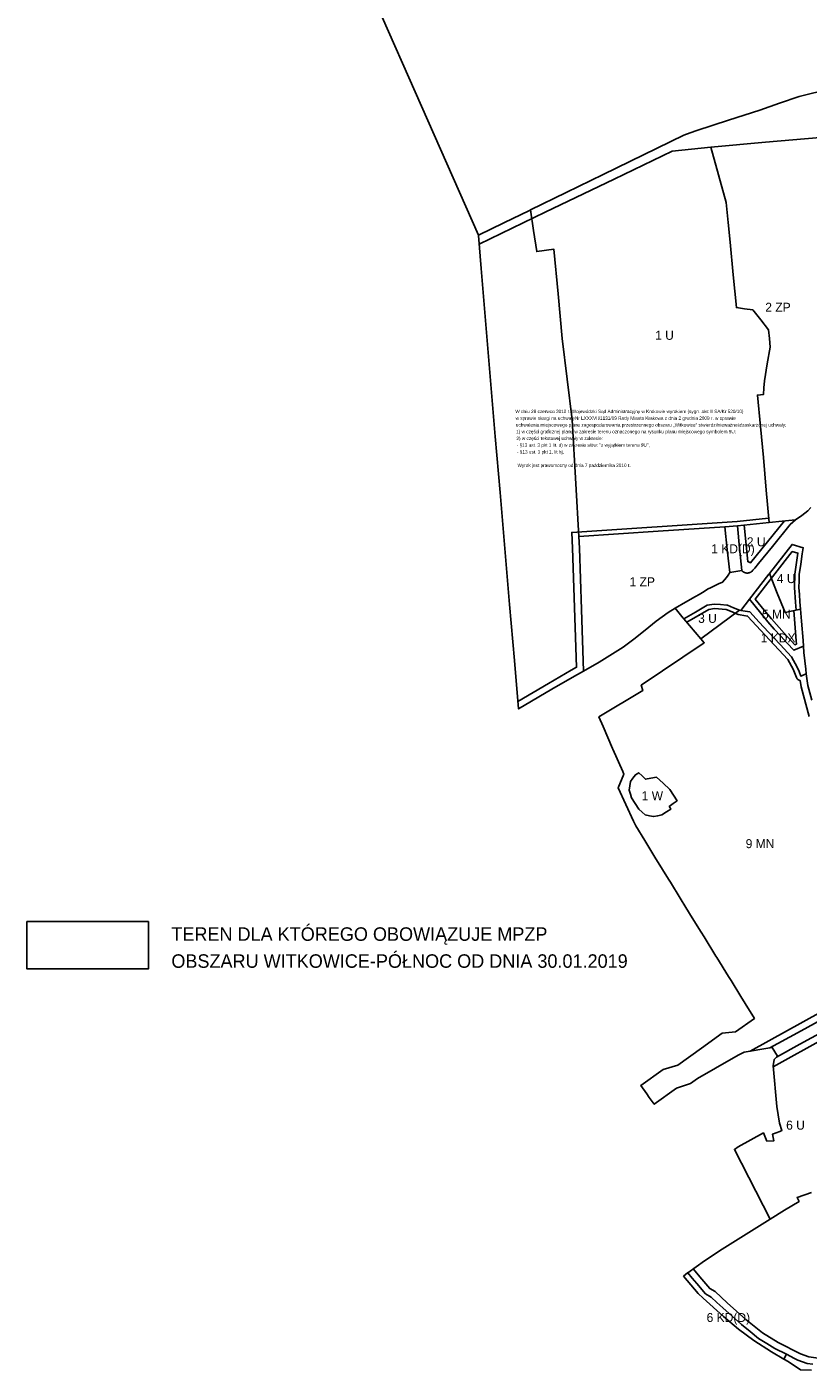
# Model space of a CAD drawing. Extents: x 7423691 to 7425475, y 5552085 to 5554331.
# Drawn here: x 7423691 to 7424385, y 5552233 to 5553427 of the extents above; entities that cross this region are included whole.
import ezdxf

# ---------------------------------------------------------------- set-up
doc = ezdxf.new("R2010")
doc.units = 0
for name, color, linetype in [('linia_zabudowy_nieprzekraczalna', 7, 'Continuous'), ('linie_rozgraniczajace', 7, 'Continuous'), ('oznaczenia_przeznaczen', 7, 'Continuous'), ('Witkowice_Północ', 7, 'Continuous')]:
    doc.layers.add(name, color=color, linetype=linetype)

msp = doc.modelspace()

# ---------------------------------------------------------------- linework, layer by layer
at = {"layer": 'linia_zabudowy_nieprzekraczalna'}
for points in [[(7424298.81, 5553320.3), (7424264.38, 5553316.64), (7424212.77, 5553291.84), (7424151.55, 5553262.41), (7424092.82, 5553234.06)], [(7424127.29, 5552827.27), (7424154.54, 5552843.37), (7424174.66, 5552855.11), (7424179.44, 5552857.77), (7424175.9, 5552963.47), (7424175.11, 5552977.64), (7424322.2, 5552987.46), (7424350.09, 5552990.32)], [(7424328.51, 5552984.08), (7424331.55, 5552951.67), (7424333.94, 5552950.56), (7424364.31, 5552987.77)], [(7424372.58, 5552908.11), (7424374.77, 5552881.2), (7424374.92, 5552878.26), (7424373.57, 5552877.7), (7424363.83, 5552888.08), (7424352.56, 5552900.66), (7424346.09, 5552908.44), (7424338.3, 5552918.22), (7424371.15, 5552960.64), (7424376.12, 5552959.29), (7424376.12, 5552959.29), (7424373.38, 5552940.61), (7424373.08, 5552928.5), (7424373.97, 5552915.68), (7424374.56, 5552908.48)], [(7424335.78, 5552914.96), (7424335.48, 5552914.58)], [(7424277.33, 5552897.7), (7424296.98, 5552908.96), (7424302, 5552909.9), (7424312.48, 5552909.08), (7424316.21, 5552907.66), (7424323.09, 5552904.53), (7424324.84, 5552904.25), (7424324.84, 5552904.25), (7424331.39, 5552903.18), (7424347.14, 5552886.09), (7424367.36, 5552864.64), (7424372.07, 5552855.92), (7424374.97, 5552848.52), (7424375.2, 5552848.01), (7424375.49, 5552847.54), (7424375.84, 5552847.11), (7424376.26, 5552846.73), (7424376.73, 5552846.41), (7424377.23, 5552846.17), (7424377.75, 5552846), (7424378.27, 5552845.9), (7424378.95, 5552840.23), (7424386.33, 5552813.96)], [(7424397.48, 5552551.4), (7424333.75, 5552516.27)], [(7424400.4, 5552408.64), (7424408.18, 5552408.95), (7424416.39, 5552416.19), (7424421.51, 5552418.39), (7424444.81, 5552427.53), (7424458.27, 5552433.41), (7424452.84, 5552443), (7424451.24, 5552444.38), (7424431.75, 5552461.23), (7424426.13, 5552466.13), (7424417.13, 5552487.94), (7424407.39, 5552511.01), (7424400.18, 5552527.77), (7424354.16, 5552502.4)], [(7424283.11, 5552322.72), (7424290.92, 5552313.42), (7424297.88, 5552305.19), (7424302.65, 5552302.46), (7424313.35, 5552292.4), (7424329.92, 5552277.7), (7424344.76, 5552265.77), (7424358.71, 5552257.06), (7424378.55, 5552246.99), (7424385.8, 5552244.36), (7424394.2, 5552243.19), (7424396.85, 5552243.7), (7424410.23, 5552249.51)]]:
    msp.add_lwpolyline(points, dxfattribs=at)
at = {"layer": 'linie_rozgraniczajace'}
for points in [[(7424404.09, 5553447.74), (7424402.84, 5553403.8), (7424402.46, 5553397.12), (7424401.72, 5553383.77), (7424400.72, 5553370.96), (7424389.05, 5553368.17), (7424377.38, 5553365.38), (7424359.9, 5553359.31), (7424342.42, 5553353.25), (7424314.38, 5553344.13), (7424286.34, 5553335.02), (7424280.52, 5553333), (7424274.69, 5553330.99), (7424238.8, 5553313.52), (7424202.92, 5553296.05), (7424170.19, 5553280.04), (7424138.53, 5553264.56), (7424137.46, 5553264.03), (7424114.78, 5553252.97), (7424092.11, 5553241.91), (7423950.32, 5553563.7)], [(7424395.95, 5553328.82), (7424347.38, 5553324.56), (7424298.81, 5553320.3), (7424305.68, 5553295.65), (7424312.55, 5553271.01), (7424314.25, 5553253.36), (7424315.94, 5553235.71), (7424318.74, 5553206.62), (7424321.54, 5553177.54), (7424328.82, 5553176.51), (7424336.09, 5553175.48), (7424343.09, 5553166.67), (7424350.09, 5553157.85), (7424350.83, 5553150.18), (7424351.57, 5553142.5), (7424348.97, 5553127.41), (7424346.37, 5553112.32), (7424345.99, 5553106.32), (7424345.61, 5553100.32), (7424342.87, 5553100.01), (7424340.12, 5553099.71), (7424342.87, 5553071.95), (7424345.62, 5553044.18), (7424348.06, 5553015.26), (7424350.5, 5552986.34), (7424322.62, 5552983.48), (7424322.54, 5552983.47), (7424311.28, 5552982.72), (7424251.93, 5552978.76), (7424181.32, 5552974.05), (7424178.71, 5553020.69), (7424175.53, 5553077.61), (7424171.11, 5553113.79), (7424166.69, 5553149.96), (7424162.93, 5553189.75), (7424159.16, 5553229.53), (7424143.96, 5553227.43), (7424141.25, 5553245.99), (7424138.53, 5553264.56), (7424170.19, 5553280.04), (7424202.92, 5553296.05), (7424238.8, 5553313.52), (7424274.69, 5553330.99), (7424280.52, 5553333), (7424286.34, 5553335.02), (7424314.38, 5553344.13), (7424342.42, 5553353.25), (7424359.9, 5553359.31), (7424377.38, 5553365.38), (7424389.05, 5553368.17)], [(7424387.6, 5552999.9), (7424385.05, 5552996.71), (7424379.54, 5552992.74), (7424374.03, 5552988.77), (7424362.26, 5552987.56), (7424350.5, 5552986.34), (7424348.06, 5553015.26), (7424345.62, 5553044.18), (7424342.87, 5553071.95), (7424340.12, 5553099.71), (7424342.87, 5553100.01), (7424345.61, 5553100.32), (7424345.99, 5553106.32), (7424346.37, 5553112.32), (7424348.97, 5553127.41), (7424351.57, 5553142.5), (7424350.83, 5553150.18), (7424350.09, 5553157.85), (7424343.09, 5553166.67), (7424336.09, 5553175.48), (7424328.82, 5553176.51), (7424321.54, 5553177.54), (7424318.74, 5553206.62), (7424315.94, 5553235.71), (7424314.25, 5553253.36), (7424312.55, 5553271.01), (7424305.68, 5553295.65), (7424298.81, 5553320.3), (7424347.38, 5553324.56), (7424395.95, 5553328.82)], [(7424267.08, 5552910.22), (7424276.18, 5552915.44), (7424285.28, 5552920.66), (7424288.33, 5552922.43), (7424291.38, 5552924.19), (7424293.64, 5552925.63), (7424295.9, 5552927.05), (7424298.94, 5552928.63), (7424301.98, 5552930.21), (7424305.58, 5552931.75), (7424309.19, 5552933.3), (7424310.92, 5552935.42), (7424312.65, 5552937.55), (7424314.09, 5552939.69), (7424315.52, 5552941.84), (7424320.89, 5552942.79), (7424326.27, 5552943.73), (7424326.37, 5552943.61), (7424326.48, 5552943.49), (7424326.59, 5552943.37), (7424326.71, 5552943.26), (7424326.82, 5552943.15), (7424326.94, 5552943.04), (7424327.07, 5552942.94), (7424327.19, 5552942.84), (7424327.32, 5552942.74), (7424327.45, 5552942.65), (7424327.58, 5552942.56), (7424327.71, 5552942.47), (7424327.85, 5552942.39), (7424327.99, 5552942.31), (7424328.13, 5552942.23), (7424328.27, 5552942.16), (7424328.41, 5552942.09), (7424328.56, 5552942.02), (7424328.71, 5552941.96), (7424328.86, 5552941.9), (7424329.01, 5552941.84), (7424329.16, 5552941.79), (7424329.31, 5552941.74), (7424329.46, 5552941.7), (7424329.62, 5552941.66), (7424329.78, 5552941.62), (7424329.93, 5552941.59), (7424330.09, 5552941.56), (7424330.25, 5552941.54), (7424330.41, 5552941.52), (7424330.57, 5552941.5), (7424330.73, 5552941.49), (7424330.89, 5552941.48), (7424331.05, 5552941.47), (7424331.21, 5552941.47), (7424331.37, 5552941.48), (7424331.53, 5552941.48), (7424331.69, 5552941.5), (7424331.84, 5552941.51), (7424332, 5552941.53), (7424332.16, 5552941.55), (7424332.32, 5552941.58), (7424332.48, 5552941.61), (7424332.63, 5552941.65), (7424332.79, 5552941.69), (7424332.94, 5552941.73), (7424333.09, 5552941.78), (7424333.25, 5552941.83), (7424333.4, 5552941.88), (7424333.55, 5552941.94), (7424333.69, 5552942), (7424333.84, 5552942.07), (7424333.99, 5552942.14), (7424334.13, 5552942.21), (7424334.27, 5552942.29), (7424334.41, 5552942.36), (7424334.54, 5552942.45), (7424334.68, 5552942.53), (7424334.81, 5552942.62), (7424334.84, 5552942.64), (7424335.16, 5552942.98), (7424336.19, 5552944.08), (7424337.75, 5552945.73), (7424341.24, 5552950.01), (7424353.58, 5552965.14), (7424369.42, 5552984.54), (7424371.72, 5552986.66), (7424374.03, 5552988.77), (7424379.54, 5552992.74), (7424385.05, 5552996.71), (7424387.6, 5552999.9)], [(7424388.5, 5552828.42), (7424384.86, 5552841.41), (7424383.61, 5552851.8), (7424383.09, 5552856.1), (7424381.33, 5552870.79), (7424381.03, 5552876.44), (7424380.75, 5552881.6), (7424379.36, 5552898.79), (7424378.5, 5552909.37), (7424377.96, 5552915.98), (7424377.52, 5552922.29), (7424377.09, 5552928.59), (7424377.23, 5552934.43), (7424377.37, 5552940.27), (7424378.72, 5552949.46), (7424380.06, 5552958.66), (7424380.99, 5552964.04), (7424370.98, 5552966.96), (7424350.94, 5552941.07), (7424350.42, 5552940.4), (7424333.21, 5552918.18), (7424329.44, 5552913.31), (7424325.47, 5552908.19), (7424324.26, 5552908.39), (7424318.91, 5552910.67), (7424313.57, 5552912.96), (7424313.13, 5552913.04), (7424307.46, 5552913.48), (7424301.79, 5552913.93), (7424295.58, 5552912.77), (7424285.12, 5552906.77), (7424274.67, 5552900.79), (7424274.28, 5552901.25), (7424267.08, 5552910.22)], [(7424400.02, 5552545.95), (7424375.69, 5552532.54), (7424351.36, 5552519.13), (7424328.49, 5552515.42), (7424323.16, 5552512.68), (7424303.07, 5552501.21), (7424286.83, 5552491.94), (7424280.72, 5552487.55), (7424268.37, 5552483.32), (7424248.47, 5552469.03), (7424244.05, 5552475.18), (7424241.74, 5552478.41), (7424236.52, 5552485.68), (7424256.41, 5552499.97), (7424269.34, 5552503.71), (7424290.35, 5552518.81), (7424308.94, 5552532.15), (7424320.82, 5552533.36), (7424337.45, 5552545.4), (7424329.3, 5552558.63), (7424325.36, 5552565.02), (7424316.73, 5552579.01), (7424314.57, 5552582.53), (7424304.08, 5552599.57), (7424303.34, 5552600.77), (7424292.75, 5552617.95), (7424290.2, 5552622.09), (7424282.29, 5552634.94), (7424276.64, 5552644.1), (7424271.61, 5552652.27), (7424262.85, 5552666.5), (7424261.09, 5552669.35), (7424250.57, 5552686.42), (7424250, 5552687.35), (7424240.06, 5552703.49), (7424231.98, 5552716.59), (7424230.01, 5552720.91), (7424216.5, 5552750.39), (7424221.41, 5552762.6), (7424220.41, 5552764.89), (7424211.68, 5552784.97), (7424211.45, 5552785.52), (7424203, 5552804.98), (7424199.28, 5552813.54), (7424238.27, 5552837.01), (7424236.9, 5552841.75), (7424292.94, 5552879.5), (7424289.92, 5552883.01), (7424307.09, 5552895.7), (7424324.26, 5552908.39), (7424325.47, 5552908.19), (7424329.43, 5552907.55), (7424333.39, 5552906.91), (7424341.87, 5552897.72), (7424350.07, 5552888.82), (7424360.29, 5552877.98), (7424370.63, 5552867), (7424375.59, 5552857.82), (7424377.16, 5552853.84), (7424378.73, 5552849.87), (7424383.61, 5552851.8), (7424384.86, 5552841.41), (7424388.5, 5552828.42)], [(7424388.29, 5552390.66), (7424375.49, 5552386.27), (7424376.36, 5552384.46), (7424377.23, 5552382.65), (7424364.4, 5552374.76), (7424351.42, 5552366.78), (7424351.57, 5552366.87), (7424319.81, 5552428.85), (7424322.99, 5552431.29), (7424345.45, 5552443.59), (7424348.57, 5552436.25), (7424354.88, 5552436.58), (7424353.57, 5552442.32), (7424360.21, 5552444.81), (7424361.97, 5552445.64), (7424359.74, 5552452.27), (7424357.59, 5552467.12), (7424354.07, 5552503.28), (7424355.1, 5552508.75), (7424357.25, 5552510.96), (7424377.97, 5552522.38), (7424398.69, 5552533.8)], [(7424389.35, 5552237.81), (7424384.35, 5552238.5), (7424380.26, 5552239.99), (7424376.16, 5552241.47), (7424373.22, 5552242.97), (7424365.96, 5552246.65), (7424355.76, 5552251.83), (7424348.52, 5552256.35), (7424341.28, 5552260.87), (7424333.66, 5552266.99), (7424326.04, 5552273.12), (7424317.68, 5552280.54), (7424309.31, 5552287.97), (7424304.18, 5552292.78), (7424299.06, 5552297.6), (7424293.98, 5552300.51), (7424286.34, 5552309.55), (7424282.26, 5552314.4), (7424278.19, 5552319.25), (7424293.03, 5552329.74), (7424308.85, 5552340.26), (7424351.42, 5552366.78), (7424364.4, 5552374.76), (7424377.23, 5552382.65), (7424376.36, 5552384.46), (7424375.49, 5552386.27), (7424388.29, 5552390.66)], [(7424388.34, 5552232.59), (7424378.48, 5552232.85), (7424367.61, 5552240.22), (7424363.78, 5552242.4), (7424365.96, 5552246.65), (7424373.22, 5552242.97), (7424376.16, 5552241.47), (7424380.26, 5552239.99), (7424384.35, 5552238.5), (7424389.35, 5552237.81)]]:
    msp.add_lwpolyline(points, dxfattribs=at)
for points in [[(7424092.11, 5553241.91), (7424114.78, 5553252.97), (7424137.46, 5553264.03), (7424138.53, 5553264.56), (7424141.25, 5553245.99), (7424143.96, 5553227.43), (7424159.16, 5553229.53), (7424162.93, 5553189.75), (7424166.69, 5553149.96), (7424171.11, 5553113.79), (7424175.53, 5553077.61), (7424178.71, 5553020.69), (7424181.32, 5552974.05), (7424181.89, 5552963.74), (7424183.73, 5552909.03), (7424185.56, 5552854.31), (7424177.63, 5552849.89), (7424157.57, 5552838.2), (7424127.86, 5552820.64), (7424124.09, 5552863.72), (7424119.81, 5552913.52), (7424115.57, 5552963.31), (7424111.39, 5553013.12), (7424107.11, 5553062.92), (7424102.97, 5553112.73), (7424098.73, 5553162.53), (7424094.7, 5553212.35), (7424092.15, 5553241.81)], [(7424185.56, 5552854.31), (7424183.73, 5552909.03), (7424181.89, 5552963.74), (7424181.32, 5552974.05), (7424251.93, 5552978.76), (7424311.28, 5552982.72), (7424313.4, 5552962.28), (7424315.52, 5552941.84), (7424314.09, 5552939.69), (7424312.65, 5552937.55), (7424310.92, 5552935.42), (7424309.19, 5552933.3), (7424305.58, 5552931.75), (7424301.98, 5552930.21), (7424298.94, 5552928.63), (7424295.9, 5552927.05), (7424293.64, 5552925.63), (7424291.38, 5552924.19), (7424288.33, 5552922.43), (7424285.28, 5552920.66), (7424276.18, 5552915.44), (7424267.08, 5552910.22), (7424267.03, 5552910.28), (7424260.77, 5552906.29), (7424250.17, 5552898.63), (7424240.5, 5552890.8), (7424230.46, 5552882.68), (7424220.72, 5552875.51), (7424199.59, 5552862.08)], [(7424311.28, 5552982.72), (7424322.54, 5552983.47), (7424322.62, 5552983.48), (7424324.4, 5552963.6), (7424326.27, 5552943.73), (7424320.89, 5552942.79), (7424315.52, 5552941.84), (7424313.4, 5552962.28)], [(7424322.62, 5552983.48), (7424350.5, 5552986.34), (7424362.26, 5552987.56), (7424374.03, 5552988.77), (7424371.72, 5552986.66), (7424369.42, 5552984.54), (7424353.58, 5552965.14), (7424341.24, 5552950.01), (7424337.75, 5552945.73), (7424336.19, 5552944.08), (7424335.16, 5552942.98), (7424334.84, 5552942.64), (7424334.81, 5552942.62), (7424334.68, 5552942.53), (7424334.54, 5552942.45), (7424334.41, 5552942.36), (7424334.27, 5552942.29), (7424334.13, 5552942.21), (7424333.99, 5552942.14), (7424333.84, 5552942.07), (7424333.69, 5552942), (7424333.55, 5552941.94), (7424333.4, 5552941.88), (7424333.25, 5552941.83), (7424333.09, 5552941.78), (7424332.94, 5552941.73), (7424332.79, 5552941.69), (7424332.63, 5552941.65), (7424332.48, 5552941.61), (7424332.32, 5552941.58), (7424332.16, 5552941.55), (7424332, 5552941.53), (7424331.84, 5552941.51), (7424331.69, 5552941.5), (7424331.53, 5552941.48), (7424331.37, 5552941.48), (7424331.21, 5552941.47), (7424331.05, 5552941.47), (7424330.89, 5552941.48), (7424330.73, 5552941.49), (7424330.57, 5552941.5), (7424330.41, 5552941.52), (7424330.25, 5552941.54), (7424330.09, 5552941.56), (7424329.93, 5552941.59), (7424329.78, 5552941.62), (7424329.62, 5552941.66), (7424329.46, 5552941.7), (7424329.31, 5552941.74), (7424329.16, 5552941.79), (7424329.01, 5552941.84), (7424328.86, 5552941.9), (7424328.71, 5552941.96), (7424328.56, 5552942.02), (7424328.41, 5552942.09), (7424328.27, 5552942.16), (7424328.13, 5552942.23), (7424327.99, 5552942.31), (7424327.85, 5552942.39), (7424327.71, 5552942.47), (7424327.58, 5552942.56), (7424327.45, 5552942.65), (7424327.32, 5552942.74), (7424327.19, 5552942.84), (7424327.07, 5552942.94), (7424326.94, 5552943.04), (7424326.82, 5552943.15), (7424326.71, 5552943.26), (7424326.59, 5552943.37), (7424326.48, 5552943.49), (7424326.37, 5552943.61), (7424326.27, 5552943.73), (7424324.4, 5552963.6)], [(7424350.94, 5552941.07), (7424370.98, 5552966.96), (7424380.99, 5552964.04), (7424380.06, 5552958.66), (7424378.72, 5552949.46), (7424377.37, 5552940.27), (7424377.23, 5552934.43), (7424377.09, 5552928.59), (7424377.52, 5552922.29), (7424377.96, 5552915.98), (7424378.5, 5552909.37), (7424371.64, 5552907.82), (7424364.78, 5552906.27), (7424357.86, 5552923.67)], [(7424333.21, 5552918.18), (7424350.42, 5552940.4), (7424350.94, 5552941.07), (7424357.86, 5552923.67), (7424364.78, 5552906.27), (7424371.64, 5552907.82), (7424378.5, 5552909.37), (7424379.36, 5552898.79), (7424380.75, 5552881.6), (7424381.03, 5552876.44), (7424372.59, 5552872.89), (7424366.74, 5552879.13), (7424360.88, 5552885.37), (7424355.2, 5552891.71), (7424349.53, 5552898.05), (7424338.1, 5552912.05)], [(7424274.67, 5552900.79), (7424285.12, 5552906.77), (7424295.58, 5552912.77), (7424301.79, 5552913.93), (7424307.46, 5552913.48), (7424313.13, 5552913.04), (7424313.57, 5552912.96), (7424318.91, 5552910.67), (7424324.26, 5552908.39), (7424307.09, 5552895.7), (7424289.92, 5552883.01)], [(7424325.47, 5552908.19), (7424329.44, 5552913.31), (7424333.21, 5552918.18), (7424338.1, 5552912.05), (7424349.53, 5552898.05), (7424355.2, 5552891.71), (7424360.88, 5552885.37), (7424366.74, 5552879.13), (7424372.59, 5552872.89), (7424381.03, 5552876.44), (7424381.33, 5552870.79), (7424383.09, 5552856.1), (7424383.61, 5552851.8), (7424378.73, 5552849.87), (7424377.16, 5552853.84), (7424375.59, 5552857.82), (7424370.63, 5552867), (7424360.29, 5552877.98), (7424350.07, 5552888.82), (7424341.87, 5552897.72), (7424333.39, 5552906.91), (7424329.43, 5552907.55)], [(7424226.2, 5552748.45), (7424227.25, 5552744.94), (7424228.31, 5552741.43), (7424231.55, 5552736.44), (7424234.79, 5552731.44), (7424237.62, 5552728.95), (7424240.46, 5552726.45), (7424244.18, 5552725.65), (7424247.9, 5552724.85), (7424251.56, 5552725.7), (7424255.23, 5552726.55), (7424259.25, 5552729.07), (7424263.28, 5552731.59), (7424262.58, 5552732.72), (7424261.88, 5552733.84), (7424265.31, 5552736.41), (7424268.75, 5552738.98), (7424265.49, 5552744.05), (7424262.23, 5552749.11), (7424256.33, 5552754.52), (7424250.44, 5552759.93), (7424245.5, 5552759.01), (7424240.57, 5552758.08), (7424237.6, 5552761), (7424234.63, 5552763.92), (7424231.67, 5552762.07), (7424229.5, 5552759.01), (7424227.34, 5552755.96), (7424226.77, 5552752.2)], [(7424226.2, 5552748.45), (7424226.77, 5552752.2), (7424227.34, 5552755.96), (7424229.5, 5552759.01), (7424231.67, 5552762.07), (7424234.63, 5552763.92), (7424237.6, 5552761), (7424240.57, 5552758.08), (7424245.5, 5552759.01), (7424250.44, 5552759.93), (7424256.33, 5552754.52), (7424262.23, 5552749.11), (7424265.49, 5552744.05), (7424268.75, 5552738.98), (7424265.31, 5552736.41), (7424261.88, 5552733.84), (7424262.58, 5552732.72), (7424263.28, 5552731.59), (7424259.25, 5552729.07), (7424255.23, 5552726.55), (7424251.56, 5552725.7), (7424247.9, 5552724.85), (7424244.18, 5552725.65), (7424240.46, 5552726.45), (7424237.62, 5552728.95), (7424234.79, 5552731.44), (7424231.55, 5552736.44), (7424228.31, 5552741.43), (7424227.25, 5552744.94)], [(7424351.36, 5552519.13), (7424375.69, 5552532.54), (7424400.02, 5552545.95), (7424441.07, 5552561.81), (7424482.12, 5552577.67), (7424495.9, 5552585.22), (7424509.69, 5552592.76), (7424515.75, 5552584.68), (7424510.38, 5552581.74), (7424501.04, 5552576.63), (7424486.34, 5552568.58), (7424447.47, 5552553.56), (7424408.6, 5552538.54), (7424406.99, 5552534.71), (7424402.5, 5552532.49), (7424398.69, 5552533.8), (7424377.97, 5552522.38), (7424357.25, 5552510.96), (7424358.03, 5552511.76), (7424353.43, 5552519.46)], [(7424274.54, 5552316.22), (7424278.08, 5552319.17), (7424278.19, 5552319.25), (7424282.26, 5552314.4), (7424286.34, 5552309.55), (7424293.98, 5552300.51), (7424299.06, 5552297.6), (7424304.18, 5552292.78), (7424309.31, 5552287.97), (7424317.68, 5552280.54), (7424326.04, 5552273.12), (7424333.66, 5552266.99), (7424341.28, 5552260.87), (7424348.52, 5552256.35), (7424355.76, 5552251.83), (7424365.96, 5552246.65), (7424363.78, 5552242.4), (7424352.65, 5552248.76), (7424337, 5552259), (7424323.47, 5552269), (7424310.17, 5552280.3), (7424291.91, 5552296.69), (7424287.56, 5552300.73)]]:
    msp.add_lwpolyline(points, close=True, dxfattribs=at)
at = {"layer": 'Witkowice_Północ'}
msp.add_lwpolyline([(7423690.74, 5552631.56), (7423798.73, 5552631.56), (7423798.73, 5552589.47), (7423690.74, 5552589.47)], close=True, dxfattribs=at)

# ---------------------------------------------------------------- texts
at = {"layer": 'oznaczenia_przeznaczen'}
for s, height, p in [('2 ZP', 8, (7424347.16, 5553173.87)), ('1 U', 8, (7424249.27, 5553148.91)), ('W dniu 28 czerwca 2010 r. Wojewódzki Sąd Administracyjny w Krakowie wyrokiem (sygn. akt: II SA/Kr 520/10) ', 3, (7424124.96, 5553083.73)), ('w sprawie skargi na uchwałęNr LXXXVII/1131/09 Rady Miasta Krakowa z dnia 2 grudnia 2009 r. w sprawie ', 3, (7424125.2, 5553077.74)), ('uchwalenia miejscowego planu zagospodarowania przestrzennego obszaru „Witkowice" stwierdziłnieważnośćzaskarżonej uchwały: ', 3, (7424125.44, 5553071.74)), ('1) w części graficznej planu w zakresie terenu oznaczonego na rysunku planu miejscowego symbolem 9U;', 3, (7424125.69, 5553065.75)), ('2) w części tekstowej uchwały w zakresie:', 3, (7424125.93, 5553059.76)), ('- §13 ust. 3 pkt 1 lit. d) w zakresie słów: "z wyjątkiem terenu 9U",', 3, (7424126.17, 5553053.76)), ('- §13 ust. 3 pkt 1. lit h).', 3, (7424126.42, 5553047.77)), ('Wyrok jest prawomocny od dnia 7 października 2010 r.', 3, (7424126.9, 5553035.78)), ('2 U', 8, (7424330.79, 5552965.27)), ('1 KD(D)', 8, (7424299.14, 5552959.08)), ('1 ZP', 8, (7424226.5, 5552929.7)), ('4 U', 8, (7424357.43, 5552932.55)), ('3 U', 8, (7424287.47, 5552897.18)), ('5 MN', 8, (7424344.25, 5552900.92)), ('1 KDX', 8, (7424343.12, 5552879.75)), ('1 W', 8, (7424237.29, 5552739.45)), ('9 MN', 8, (7424329.78, 5552696.82)), ('6 U', 8, (7424365.72, 5552446.47)), ('6 KD(D)', 8, (7424295.03, 5552275.39))]:
    msp.add_text(s, height=height, dxfattribs=at).set_placement(p)
at = {"layer": 'Witkowice_Północ'}
for s, p in [('TEREN DLA KTÓREGO OBOWIĄZUJE MPZP ', (7423819.17, 5552614.4)), ('OBSZARU WITKOWICE-PÓŁNOC OD DNIA 30.01.2019', (7423819.17, 5552590.4))]:
    msp.add_text(s, height=12, dxfattribs=at).set_placement(p)

doc.saveas('drawing.dxf')
